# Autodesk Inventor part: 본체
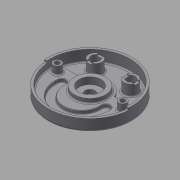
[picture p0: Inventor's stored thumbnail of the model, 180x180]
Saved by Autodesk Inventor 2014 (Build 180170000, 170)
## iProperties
Created: 2015-06
Part Number: 본체
Material: Generic
Document SubType Name: Modeling
Designer: MYHOME
Density: 1 g/cm^3
Appearance: Default
Author: MYHOME
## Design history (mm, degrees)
sketch "스케치4"
  geometry: C1 r 95 at (0, 0); 1 further point
  constraints: 1 centre point, 1 coincident
  dimensions: "d11" = 190 diameter of C1
extrude "돌출4" new body sketch "스케치4" distance "d12" = 32; taper "d13" = 0 deg
sketch "스케치5"
  geometry: C1 r 95 at (0, 0) reference; C2 r 90 at (0, 0)
  constraints: 1 centre point, 1 coincident
  dimensions: "d14" = 180 diameter of C2
extrude "돌출5" cut sketch "스케치5" distance "d15" = 25; taper "d16" = 0 deg
sketch "스케치6"
  geometry: L1 (-90, 0)-(90, 0); L2 (-88.566, 16)-(-38.833, 16); L3 (38.833, 16)-(88.566, 16); A1 r 90 centre (0, 0) between (-90, 0) and (90, 0) reference; A2 r 42 centre (0, 0) between (-38.833, 16) and (38.833, 16)
  constraints: 6 end point, 6 point on circle, 2 parallel, 1 centre point, 1 coincident, 1 horizontal, 1 midpoint
  dimensions: "d17" = 84 diameter of A2; "d19" = 16 distance between parallel lines of L1 L2; "d20" = 16 distance between parallel lines of L1 L3
extrude "돌출6" join sketch "스케치6" distance "d21" = 7; taper "d22" = 0 deg
sketch "스케치8"
  geometry: C1 r 95 at (0, 0) reference; C2 r 11.5 at (0, 0)
  constraints: 1 centre point, 1 coincident
  dimensions: "d37" = 23 diameter of C2
extrude "돌출7" cut sketch "스케치8" stored distance "d38" = 7; taper "d39" = 0 deg
sketch "스케치18"
  geometry: C1 r 15 at (-40, 52); C2 r 15 at (40, 52); A1 r 42 centre (0, 0) between (38.833, 16) and (-38.833, 16) reference
  constraints: 2 centre point
  dimensions: "d57" = 30 diameter of C1; "d58" = 30 diameter of C2; "d59" = 40 horizontal distance of A1.centre C1.centre; "d60" = 80 distance of C2.centre C1.centre; "d61" = 52 vertical distance of A1.centre C1.centre; "d62" = 52 vertical distance of A1.centre C2.centre
extrude "돌출11" join sketch "스케치18" distance "d63" = 25; taper "d64" = 0 deg
sketch "스케치19"
  geometry: C1 r 15 at (0, 0) reference; C2 r 15 at (80, 0) reference; C3 r 10 at (0, 0); C4 r 10 at (80, 0); 1 further point
  constraints: 2 centre point, 2 coincident
  dimensions: "d65" = 20 diameter of C3; "d66" = 20 diameter of C4
extrude "돌출14" cut sketch "스케치19" stored distance "d71" = 25; taper "d72" = 0 deg
sketch "스케치20"
  geometry: L1 (-6, 15)-(6, 15); L2 (6, 15)-(6, -15); L3 (6, -15)-(-6, -15); L4 (-6, -15)-(-6, 15); L5 (65, 6)-(95, 6); L6 (95, 6)-(95, -6); L7 (95, -6)-(65, -6); L8 (65, -6)-(65, 6); C1 r 10 at (0, 0) reference; C2 r 15 at (80, 0) reference; C3 r 10 at (80, 0) reference; 6 further points
  constraints: 16 end point, 4 midpoint, 4 parallel, 3 vertical alignment, 2 horizontal, 2 perpendicular, 1 horizontal alignment, 1 other
  dimensions: "d73" = 12 distance of L2.end L3.end; "d74" = 30 distance of L1.end L2.end; "d75" = 30 distance of L6.end L7.end; "d76" = 12 distance of L7.end L5.start
extrude "돌출15" cut sketch "스케치20" distance "d77" = 3; taper "d78" = 0 deg
sketch "스케치21"
  geometry: L1 (-58.738, -13.549)-(-58.989, -18.549); L2 (-40.761, -14.451)-(-40.999, -19.214); L3 (41, -14)-(41, -19); L4 (59, -14)-(59, -19); C1 r 11.5 at (0, 0) reference; A1 r 50 centre (0, -19) between (-50, -19) and (50, -19); A2 r 59 centre (0, -19) between (-59, -19) and (59, -19); A3 r 41 centre (0, -19) between (-41, -19) and (41, -19); A4 r 9 centre (-50, -19) between (-41, -19) and (-59, -19); A5 r 9 centre (50, -19) between (59, -19) and (41, -19); A6 r 9 centre (-49.749, -14) between (-58.738, -13.549) and (-40.761, -14.451); A7 r 9 centre (50, -14) between (59, -14) and (41, -14)
  constraints: 17 point on circle, 10 tangent, 8 end point, 7 centre point, 2 vertical alignment
  dimensions: "d79" = 41 radius of A3; "d80" = 59 radius of A2; "d81" = 19 distance of C1.centre A1.centre; "d82" = 18 distance of L3.end L4.end; "d83" = 18 distance of A3.start A2.start; "d84" = 18 diameter of A6; "d87" = 5 vertical distance of A1.start A6.centre; "d88" = 18 diameter of A7; "d89" = 5 distance of A1.end A7.centre
extrude "돌출16" cut sketch "스케치21" distance "d90" = 7; taper "d91" = 0 deg
sketch "스케치23"
  geometry: C1 r 11.5 at (0, 0) reference; C2 r 35 at (0, 0); A1 r 42 centre (0, 0) between (38.833, 16) and (-38.833, 16) reference
  constraints: 1 centre point, 1 coincident
  dimensions: "d92" = 70 diameter of C2
extrude "돌출17" join sketch "스케치23" distance "d93" = 10; taper "d94" = 0 deg
sketch "스케치25"
  geometry: L1 (0, 0)-(95, 0); L2 (0, 0)-(94.638, -8.28); L3 (0, 0)-(-94.638, -8.28); A1 r 90 centre (0, 0) between (-89.658, -7.844) and (89.658, -7.844) reference; A2 r 95 centre (0, 0) between (95, 0) and (-94.638, -8.28) reference
  constraints: 6 end point, 5 point on circle, 2 point on line, 1 horizontal
  dimensions: "d99" = 5 deg angle of L1 L3; "d100" = 5 deg angle of L1 L2
extrude "돌출18" cut sketch "스케치25" distance "d101" = 5; taper "d102" = 0 deg
sketch "스케치26"
  geometry: C1 r 35 at (0, 0) reference; C2 r 9 at (-74, 0); C3 r 9 at (74, 0); A1 r 90 centre (0, 0) between (-88.566, 16) and (88.566, 16) reference
  constraints: 2 centre point, 2 horizontal alignment
  dimensions: "d103" = 18 diameter of C2; "d104" = 18 diameter of C3; "d105" = 148 distance of C3.centre C2.centre; "d106" = 74 distance of C1.centre C2.centre
extrude "돌출19" join sketch "스케치26" stored distance "d107" = 5; taper "d108" = 0 deg
sketch "스케치27"
  geometry: C1 r 9 at (0, 0) reference; C2 r 5.5 at (0, 0); C3 r 9 at (-148, 0) reference; C4 r 5.5 at (-148, 0); 1 further point
  constraints: 2 centre point, 2 coincident
  dimensions: "d109" = 11 diameter of C2; "d110" = 11 diameter of C4
extrude "돌출20" cut sketch "스케치27" stored distance "d111" = 5; taper "d112" = 0 deg
sketch "스케치28"
  geometry: C1 r 11.5 at (0, 0) reference; C2 r 95 at (0, 0) reference; A1 r 68 centre (0, 0) between (-20.283, -64.905) and (0, -68)
  constraints: 2 point on circle, 1 centre point, 1 coincident, 1 vertical alignment, 1 other
  dimensions: "d114" = 68 radius of A1
feature "엠보싱1" sketch "스케치28" dims "d115" = 0.5, "d116" = 0
fillet "모깎기1" dims "d117" = 3
fillet "모깎기2" dims "d118" = 3
fillet "모깎기3" dims "d119" = 3
fillet "모깎기4" dims "d120" = 1
sketch "스케치29"
  geometry: C1 r 11.5 at (0, 0) reference; C2 r 35 at (0, 0) reference; C3 r 25 at (0, 0)
  constraints: 1 centre point, 1 coincident
  dimensions: "d121" = 50 diameter of C3
extrude "돌출21" cut sketch "스케치29" distance "d122" = 15; taper "d123" = 0 deg
fillet "모깎기6" dims "d125" = 5
fillet "모깎기7" dims "d127" = 3
fillet "모깎기8" dims "d128" = 3
fillet "모깎기9" dims "d129" = 1
fillet "모깎기10" dims "d130" = 0.3
node "솔리드2"
other parameters: "d8" = 16, "d18" = 16
